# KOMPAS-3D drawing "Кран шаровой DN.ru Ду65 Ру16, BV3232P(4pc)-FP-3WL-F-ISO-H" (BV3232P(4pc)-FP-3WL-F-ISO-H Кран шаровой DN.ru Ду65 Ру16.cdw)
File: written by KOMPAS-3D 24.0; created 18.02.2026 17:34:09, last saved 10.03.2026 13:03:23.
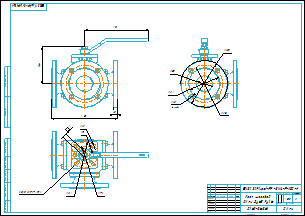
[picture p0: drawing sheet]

Document properties: Автор: R2D2; Форматы листов документа: A2; Полное имя файла: BV3232P(4pc)-FP-3WL-F-ISO-H Кран шаровой DN.ru Ду65 Ру16.m3d; Масса: 26.5; Наименование: Кран шаровой DN.ru Ду65 Ру16; Количество листов документа: 1; Примечание: D160-36361

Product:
- Part/product: Кран шаровой DN.ru Ду65 Ру16  | designation BV3232P(4pc)-FP-3WL-F-ISO-H
    Масса: 26.5
    Раздел спецификации: Прочие изделия
    Примечание: D160-36361

Views: Проекционный вид 2
Referenced files in E:\Работа\Зайцев\BV3232P(4pc)-FP-3WL-F-ISO-H Кран шаровой DN.ru Ду15-100 Ру16\DN65\: BV3232P(4pc)-FP-3WL-F-ISO-H Кран шаровой DN.ru Ду65 Ру16.m3d
Referenced files in E:\Работа\Зайцев\Для компаса\: чертеж DN.ru А3.cdt
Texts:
  BV3232P(4pc)-FP-3WL-F-ISO-H
  чертеж DN.ru А3.cdt
  Кран шаровой
  DN.ru Ду65 Ру16
  Кран шаровой DN.ru Ду65 Ру16
  BV3232P(4pc)-FP-3WL-F-ISO-H Кран шаровой DN.ru Ду65 Ру16
Dimensions and other numbers on the sheet: 0; 3; 4; 185; 145; 122; 18; 4 отв.; 65; 1:2; 1; 2; 26,5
